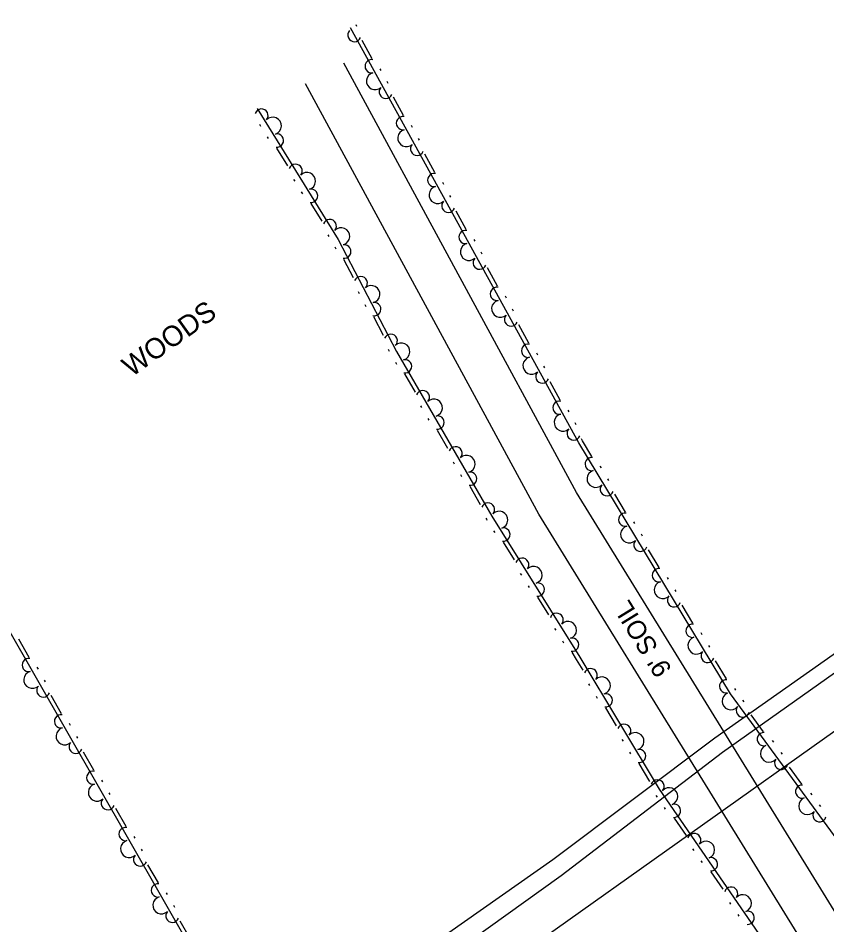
# Model space of a CAD drawing. Extents: x 1577032 to 1581865, y 611492 to 615011.
# Drawn here: x 1579472.6 to 1579630.9, y 613303 to 613480.5 of the extents above; entities that cross this region are included whole.
import ezdxf

# ---------------------------------------------------------------- set-up
doc = ezdxf.new("R2010")
doc.units = 0
for name, color, linetype in [('Exist Right of Way Line', 7, 'Continuous'), ('Exist Utilities Telephone UG FO SUE LOS B', 7, 'Continuous'), ('Exist Utilities Water UG Line SUE LOS B', 7, 'Continuous'), ('Exist Vegetation Woods Line Text', 7, 'Continuous'), ('Old_Level_11', 7, 'Continuous'), ('Scratch_Level_4', 7, 'Continuous')]:
    doc.layers.add(name, color=color, linetype=linetype)

msp = doc.modelspace()

# ---------------------------------------------------------------- linework, layer by layer
at = {"layer": 'Exist Right of Way Line'}
msp.add_line((1579178.76, 613018.8), (1580074.87, 613655.16), dxfattribs=at)
at = {"layer": 'Exist Utilities Telephone UG FO SUE LOS B'}
msp.add_lwpolyline([(1579251.42, 613079.81), (1579314.27, 613123.97), (1579356.61, 613152.5), (1579497.4, 613253.81), (1579521.61, 613271), (1579539.5, 613284.38), (1579578.9, 613312.67), (1579610.42, 613336.81), (1579656.92, 613369.78), (1579663.28, 613373.7), (1579685.42, 613390.38), (1579744.99, 613433.57), (1579762.43, 613445.5), (1579805.52, 613477.49)], dxfattribs=at)
at = {"layer": 'Exist Utilities Water UG Line SUE LOS B'}
for p, q in [((1579608.93, 613339.63), (1579657.38, 613373.69)), ((1579577.22, 613315.81), (1579608.93, 613339.63)), ((1579521.74, 613276.85), (1579577.22, 613315.81))]:
    msp.add_line(p, q, dxfattribs=at)
at = {"layer": 'Old_Level_11'}
for points in [[(1579668.31, 613574.9), (1579674.96, 613547.45), (1579676.53, 613532.3), (1579675.8, 613513.47), (1579676.54, 613496.46), (1579676.51, 613478.85), (1579676.6, 613462.83), (1579677.63, 613443.92), (1579681.14, 613430.42), (1579681.23, 613408.68), (1579684.32, 613387.86), (1579693.46, 613371.76), (1579706.72, 613349.62), (1579642.32, 613306.79), (1579612.01, 613348.24), (1579582.34, 613397.36), (1579537.68, 613478.58)], [(1579538.92, 613478.86), (1579538.75, 613479.17)], [(1579541.92, 613472.56), (1579539.94, 613476.15)], [(1579543.66, 613470.24), (1579543.47, 613470.6)], [(1579545.05, 613467.72), (1579544.85, 613468.08)], [(1579548.05, 613461.42), (1579546.07, 613465.01)], [(1579519.38, 613462.82), (1579535.23, 613437.16), (1579546.64, 613415.23), (1579565.32, 613383.01), (1579582.54, 613355.4), (1579598.04, 613329.57), (1579623.1, 613293.15), (1579581.22, 613263.04)], [(1579519.84, 613459.73), (1579520.06, 613459.38)], [(1579549.79, 613459.1), (1579549.59, 613459.46)], [(1579521.35, 613457.29), (1579521.57, 613456.94)], [(1579551.17, 613456.58), (1579550.97, 613456.94)], [(1579523.21, 613455.06), (1579525.36, 613451.57)], [(1579554.17, 613450.28), (1579552.2, 613453.87)], [(1579526.52, 613448.91), (1579526.74, 613448.57)], [(1579555.91, 613447.96), (1579555.72, 613448.32)], [(1579528.03, 613446.47), (1579528.25, 613446.12)], [(1579529.89, 613444.24), (1579532.05, 613440.76)], [(1579557.3, 613445.44), (1579557.1, 613445.8)], [(1579560.3, 613439.14), (1579558.32, 613442.73)], [(1579533.21, 613438.1), (1579533.42, 613437.75)], [(1579562.04, 613436.82), (1579561.84, 613437.18)], [(1579534.61, 613435.7), (1579534.8, 613435.33)], [(1579563.42, 613434.3), (1579563.23, 613434.66)], [(1579536.3, 613433.34), (1579538.19, 613429.7)], [(1579566.42, 613428), (1579564.45, 613431.59)], [(1579539.15, 613426.97), (1579539.34, 613426.6)], [(1579568.17, 613425.68), (1579567.97, 613426.04)], [(1579540.48, 613424.42), (1579540.66, 613424.06)], [(1579569.55, 613423.16), (1579569.35, 613423.52)], [(1579542.16, 613422.06), (1579544.06, 613418.42)], [(1579572.55, 613416.86), (1579570.57, 613420.45)], [(1579545.02, 613415.69), (1579545.21, 613415.32)], [(1579574.29, 613414.54), (1579574.1, 613414.9)], [(1579546.44, 613413.13), (1579546.64, 613412.77)], [(1579575.68, 613412.02), (1579575.48, 613412.38)], [(1579548.23, 613410.85), (1579550.29, 613407.3)], [(1579578.68, 613405.72), (1579576.7, 613409.31)], [(1579581.22, 613263.04), (1579543.09, 613234.38), (1579445.72, 613404.52)], [(1579551.38, 613404.61), (1579551.58, 613404.26)], [(1579580.42, 613403.4), (1579580.22, 613403.76)], [(1579552.82, 613402.13), (1579553.02, 613401.78)], [(1579581.8, 613400.88), (1579581.6, 613401.24)], [(1579554.61, 613399.85), (1579556.67, 613396.31)], [(1579584.91, 613394.68), (1579583.05, 613397.77), (1579582.83, 613398.17)], [(1579557.75, 613393.62), (1579557.96, 613393.26)], [(1579586.75, 613392.44), (1579586.54, 613392.79)], [(1579559.19, 613391.14), (1579559.4, 613390.78)], [(1579588.23, 613389.98), (1579588.02, 613390.33)], [(1579560.99, 613388.86), (1579563.05, 613385.31)], [(1579591.49, 613383.8), (1579589.37, 613387.31)], [(1579564.13, 613382.62), (1579564.27, 613382.38), (1579564.36, 613382.24)], [(1579593.32, 613381.55), (1579593.11, 613381.9)], [(1579565.66, 613380.14), (1579565.88, 613379.8)], [(1579594.81, 613379.1), (1579594.59, 613379.45)], [(1579567.53, 613377.93), (1579569.7, 613374.45)], [(1579598.06, 613372.92), (1579595.94, 613376.43)], [(1579570.87, 613371.79), (1579571.09, 613371.44)], [(1579599.9, 613370.67), (1579599.69, 613371.02)], [(1579572.39, 613369.36), (1579572.6, 613369.01)], [(1579601.38, 613368.22), (1579601.17, 613368.57)], [(1579574.25, 613367.14), (1579576.42, 613363.66)], [(1579604.64, 613362.04), (1579602.52, 613365.55)], [(1579577.59, 613361.01), (1579577.81, 613360.66)], [(1579606.47, 613359.79), (1579606.26, 613360.14)], [(1579474.81, 613355.34), (1579472.78, 613358.9)], [(1579579.11, 613358.57), (1579579.33, 613358.22)], [(1579607.96, 613357.33), (1579607.74, 613357.69)], [(1579580.98, 613356.35), (1579581.84, 613354.97), (1579583.11, 613352.86)], [(1579611.21, 613351.15), (1579609.09, 613354.66)], [(1579476.59, 613353.05), (1579476.39, 613353.41)], [(1579478.02, 613350.56), (1579477.82, 613350.92)], [(1579584.23, 613350.19), (1579584.44, 613349.84)], [(1579613.04, 613348.91), (1579612.83, 613349.26)], [(1579481.13, 613344.31), (1579479.09, 613347.87)], [(1579585.71, 613347.73), (1579585.92, 613347.37)], [(1579614.68, 613346.68), (1579614.44, 613347.01)], [(1579587.54, 613345.47), (1579589.65, 613341.96)], [(1579618.46, 613340.81), (1579616.04, 613344.12)], [(1579482.91, 613342.02), (1579482.7, 613342.38)], [(1579484.34, 613339.53), (1579484.13, 613339.88)], [(1579590.78, 613339.29), (1579590.99, 613338.93)], [(1579620.49, 613338.74), (1579620.24, 613339.07)], [(1579487.44, 613333.27), (1579485.41, 613336.83)], [(1579592.25, 613336.83), (1579592.46, 613336.47)], [(1579622.18, 613336.42), (1579621.94, 613336.75)], [(1579594.08, 613334.57), (1579596.19, 613331.06)], [(1579625.96, 613330.55), (1579623.54, 613333.86)], [(1579489.22, 613330.98), (1579489.02, 613331.34)], [(1579490.65, 613328.49), (1579490.45, 613328.85)], [(1579597.39, 613328.34), (1579597.63, 613328)], [(1579627.99, 613328.47), (1579627.75, 613328.8)], [(1579493.76, 613322.24), (1579491.72, 613325.8)], [(1579599.02, 613325.98), (1579599.25, 613325.64)], [(1579629.69, 613326.15), (1579629.44, 613326.49)], [(1579600.98, 613323.85), (1579603.31, 613320.47)], [(1579495.54, 613319.95), (1579495.34, 613320.31)], [(1579496.96, 613317.46), (1579496.76, 613317.82)], [(1579604.6, 613317.87), (1579604.83, 613317.53)], [(1579500.07, 613311.21), (1579498.03, 613314.76)], [(1579606.23, 613315.5), (1579606.46, 613315.17)], [(1579608.19, 613313.37), (1579610.51, 613309.99)], [(1579501.85, 613308.92), (1579501.65, 613309.27)], [(1579503.28, 613306.42), (1579503.08, 613306.78)], [(1579611.8, 613307.39), (1579612.04, 613307.06)], [(1579613.43, 613305.03), (1579613.66, 613304.69)], [(1579506.39, 613300.17), (1579504.35, 613303.73)]]:
    msp.add_lwpolyline(points, dxfattribs=at)
for centre, radius, start, end in [((1579538.44, 613477.19), 1.3, 137.2413, 338.0379), ((1579541.8, 613471.08), 1.3, 79.5748, 280.3714), ((1579542.46, 613468.17), 1.69, 104.7701, 312.8426), ((1579544.56, 613466.05), 1.3, 137.2413, 338.0379), ((1579520.24, 613461.42), 1.3, 320.1547, 160.9513), ((1579522.45, 613459.41), 1.69, 287.6836, 135.756), ((1579547.92, 613459.94), 1.3, 79.5748, 280.3714), ((1579548.59, 613457.03), 1.69, 104.7701, 312.8426), ((1579523.26, 613456.54), 1.3, 262.4883, 103.2848), ((1579550.69, 613454.91), 1.3, 137.2413, 338.0379), ((1579526.92, 613450.61), 1.3, 320.1547, 160.9513), ((1579529.13, 613448.6), 1.69, 287.6836, 135.756), ((1579554.05, 613448.8), 1.3, 79.5748, 280.3714), ((1579529.94, 613445.72), 1.3, 262.4883, 103.2848), ((1579554.71, 613445.89), 1.69, 104.7701, 312.8426), ((1579556.81, 613443.77), 1.3, 137.2413, 338.0379), ((1579533.61, 613439.79), 1.3, 320.1547, 160.9513), ((1579535.82, 613437.78), 1.69, 287.6836, 135.756), ((1579560.17, 613437.66), 1.3, 79.5748, 280.3714), ((1579536.46, 613434.81), 1.3, 258.2499, 99.0465), ((1579560.84, 613434.75), 1.69, 104.7701, 312.8426), ((1579562.94, 613432.63), 1.3, 137.2413, 338.0379), ((1579539.67, 613428.63), 1.3, 315.9164, 156.713), ((1579541.73, 613426.46), 1.69, 283.4452, 131.5177), ((1579566.3, 613426.52), 1.3, 79.5748, 280.3714), ((1579542.32, 613423.53), 1.3, 258.2499, 99.0465), ((1579566.96, 613423.61), 1.69, 104.7701, 312.8426), ((1579569.07, 613421.49), 1.3, 137.2413, 338.0379), ((1579545.54, 613417.35), 1.3, 315.9164, 156.713), ((1579547.59, 613415.22), 1.69, 286.0737, 134.1462), ((1579572.42, 613415.38), 1.3, 79.5748, 280.3714), ((1579573.09, 613412.47), 1.69, 104.7701, 312.8426), ((1579548.33, 613412.33), 1.3, 260.8784, 101.675), ((1579575.19, 613410.35), 1.3, 137.2413, 338.0379), ((1579551.82, 613406.3), 1.3, 318.5449, 159.3414), ((1579553.97, 613404.23), 1.69, 286.0737, 134.1462), ((1579578.55, 613404.24), 1.3, 79.5748, 280.3714), ((1579554.7, 613401.33), 1.3, 260.8784, 101.675), ((1579579.21, 613401.33), 1.69, 104.7701, 312.8426), ((1579581.32, 613399.21), 1.3, 137.2413, 338.0379), ((1579558.2, 613395.3), 1.3, 318.5449, 159.3414), ((1579560.35, 613393.23), 1.69, 286.0737, 134.1462), ((1579584.85, 613393.2), 1.3, 81.9074, 282.704), ((1579561.08, 613390.33), 1.3, 260.8784, 101.675), ((1579585.63, 613390.32), 1.69, 107.1027, 315.1751), ((1579587.82, 613388.29), 1.3, 139.5738, 340.3704), ((1579564.58, 613384.3), 1.3, 318.5449, 159.3414), ((1579566.75, 613382.27), 1.69, 287.9013, 135.9738), ((1579591.42, 613382.32), 1.3, 81.9074, 282.704), ((1579567.57, 613379.4), 1.3, 262.7061, 103.5026), ((1579592.2, 613379.44), 1.69, 107.1027, 315.1751), ((1579594.39, 613377.41), 1.3, 139.5738, 340.3704), ((1579571.26, 613373.49), 1.3, 320.3725, 161.1691), ((1579573.48, 613371.49), 1.69, 287.9013, 135.9738), ((1579598, 613371.44), 1.3, 81.9074, 282.704), ((1579574.3, 613368.62), 1.3, 262.7061, 103.5026), ((1579598.78, 613368.56), 1.69, 107.1027, 315.1751), ((1579600.96, 613366.53), 1.3, 139.5738, 340.3704), ((1579577.99, 613362.7), 1.3, 320.3725, 161.1691), ((1579580.2, 613360.7), 1.69, 287.9013, 135.9738), ((1579604.57, 613360.56), 1.3, 81.9074, 282.704), ((1579581.02, 613357.83), 1.3, 262.7061, 103.5026), ((1579605.35, 613357.68), 1.69, 107.1027, 315.1751), ((1579607.54, 613355.64), 1.3, 139.5738, 340.3704), ((1579474.71, 613353.87), 1.3, 80.5497, 281.3462), ((1579475.43, 613350.97), 1.69, 105.7449, 313.8174), ((1579584.65, 613351.87), 1.3, 319.4089, 160.2054), ((1579586.83, 613349.84), 1.69, 286.9377, 135.0102), ((1579611.14, 613349.68), 1.3, 81.9074, 282.704), ((1579477.56, 613348.88), 1.3, 138.2161, 339.0127), ((1579587.61, 613346.95), 1.3, 261.7424, 102.539), ((1579612.05, 613346.79), 1.69, 112.1366, 320.2091), ((1579614.41, 613344.96), 1.3, 144.6078, 345.4043), ((1579481.03, 613342.83), 1.3, 80.5497, 281.3462), ((1579481.74, 613339.93), 1.69, 105.7449, 313.8174), ((1579591.2, 613340.97), 1.3, 319.4089, 160.2054), ((1579593.38, 613338.94), 1.69, 286.9377, 135.0102), ((1579618.53, 613339.33), 1.3, 86.9413, 287.7379), ((1579483.88, 613337.85), 1.3, 138.2161, 339.0127), ((1579619.56, 613336.53), 1.69, 112.1366, 320.2091), ((1579594.15, 613336.05), 1.3, 261.7424, 102.539), ((1579621.91, 613334.7), 1.3, 144.6078, 345.4043), ((1579487.34, 613331.8), 1.3, 80.5497, 281.3462), ((1579597.74, 613330.07), 1.3, 319.4089, 160.2054), ((1579488.06, 613328.9), 1.69, 105.7449, 313.8174), ((1579600.01, 613328.15), 1.69, 290.491, 138.5635), ((1579626.03, 613329.07), 1.3, 86.9413, 287.7379), ((1579490.19, 613326.81), 1.3, 138.2161, 339.0127), ((1579627.06, 613326.27), 1.69, 112.1366, 320.2091), ((1579600.96, 613325.32), 1.3, 265.2957, 106.0923), ((1579629.42, 613324.44), 1.3, 144.6078, 345.4043), ((1579493.66, 613320.76), 1.3, 80.5497, 281.3462), ((1579604.91, 613319.58), 1.3, 322.9622, 163.7588), ((1579494.37, 613317.86), 1.69, 105.7449, 313.8174), ((1579607.22, 613317.68), 1.69, 290.491, 138.5635), ((1579496.51, 613315.78), 1.3, 138.2161, 339.0127), ((1579608.17, 613314.85), 1.3, 265.2957, 106.0923), ((1579499.97, 613309.73), 1.3, 80.5497, 281.3462), ((1579612.12, 613309.11), 1.3, 322.9622, 163.7588), ((1579500.68, 613306.83), 1.69, 105.7449, 313.8174), ((1579614.42, 613307.21), 1.69, 290.491, 138.5635), ((1579502.82, 613304.75), 1.3, 138.2161, 339.0127), ((1579615.37, 613304.38), 1.3, 265.2957, 106.0923)]:
    msp.add_arc(centre, radius, start, end, dxfattribs=at)
at = {"layer": 'Scratch_Level_4'}
for points in [[(1579650.75, 613275.86), (1579581.91, 613387.66), (1579536.35, 613471.68)], [(1579643.48, 613271.39), (1579574.52, 613383.38), (1579528.85, 613467.61)]]:
    msp.add_lwpolyline(points, dxfattribs=at)

# ---------------------------------------------------------------- texts
at = {"layer": 'Exist Vegetation Woods Line Text'}
msp.add_text('WOODS', height=4, rotation=35.38, dxfattribs=at).set_placement((1579494.83, 613410.14))
at = {"layer": 'Scratch_Level_4'}
msp.add_text("9' SOIL", height=3.691, rotation=121.6226, dxfattribs=at).set_placement((1579600.64, 613352.98))

doc.saveas('drawing.dxf')
